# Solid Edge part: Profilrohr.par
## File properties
Dokumentum tartalom típus: 0
Last saved by: bmolnar
Revision: 78
Sűrűség: 0,000 kg/m^3
Pontosság: 0,990
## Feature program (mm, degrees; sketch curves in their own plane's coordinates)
base feature "unnamed BaseFeature 1"
thread "unnamed Thread 1"
thread "Menet_2"  ThreadDepth = 7.5 mm
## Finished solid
Body 1: solid body, 157 faces, 384 edges, 264 vertices.
  Faces by surface: plane 102, cylinder 41, cone 10, torus 4
  Edges by curve: line 284, circle 92, curve on surface 8
Bounding box of the edges (mm; curved faces can reach further): 80.000 x 86.000 x 52.000, from (-40, -40, 0) to (40, 46, 52).
Cylindrical faces by radius (mm): R1.6 x2, R4.283 x4, R4.55 x7, R4.555 x1, R7 x16, R31.5 x1, R32.35 x2, R32.55 x2, R34.1 x2, R53 x4
Conical faces (half-angle, radius in mm at the cone's reference point): 30 deg R31.825 x2, 30 deg R32.6387 x2, 45 deg R4.533 x2, 45 deg R32.7 x2, 45 deg R32.8 x2
Toroidal faces (ring radius, tube radius in mm): R33.9 r0.2 x4
Planar faces by outward normal: +x 9, +y 11, +z 8, -x 9, -y 9, -z 8, oblique 48
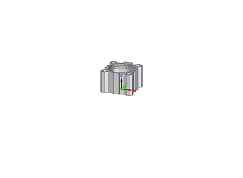
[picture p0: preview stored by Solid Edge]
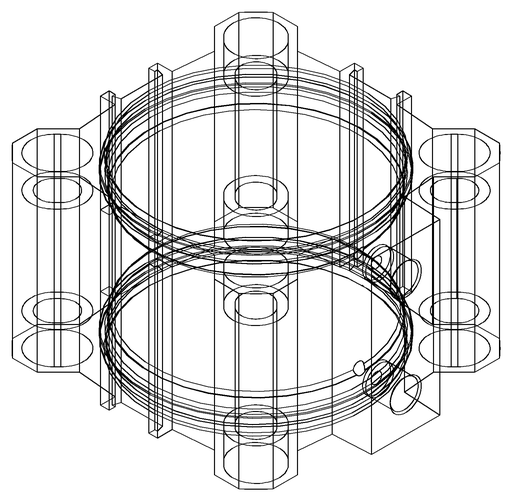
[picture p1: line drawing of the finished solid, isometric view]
